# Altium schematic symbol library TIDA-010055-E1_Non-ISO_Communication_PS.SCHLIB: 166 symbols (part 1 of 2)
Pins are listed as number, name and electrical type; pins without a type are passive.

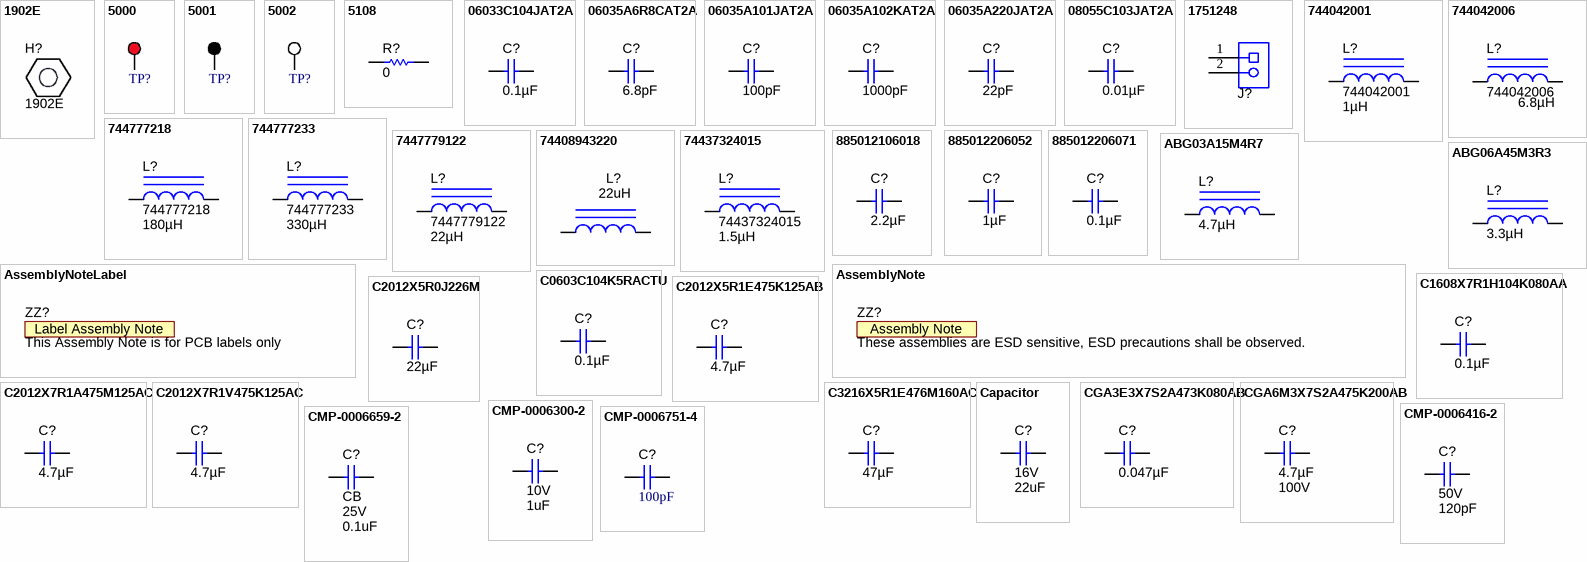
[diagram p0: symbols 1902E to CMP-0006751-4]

## 1902E
designator H?
Standoff, Hex, 1"L #4-40 Nylon; Manufacturer: Keystone; CompType: Hardware; SymbolCreator: a0412235
footprint Keystone_1902E

## 5000
designator TP?  (value not drawn)
Test Point, Miniature, Red, TH; Manufacturer: Keystone; CompType: Test Point Loop; ContactFinish: Silver; Green_Lifecycle: Active; Green_REACh: Passed
footprint Keystone5000
pins: 1

## 5001
designator TP?  (value not drawn)
Test Point, Miniature, Black, TH; Manufacturer: Keystone; CompType: Test Point Loop; ContactFinish: Silver; Green_Lifecycle: Active; Green_REACh: Passed
footprint Keystone5001
pins: 1

## 5002
designator TP?  (value not drawn)
Test Point, Miniature, White, TH; Manufacturer: Keystone; CompType: Test Point Loop; ContactFinish: Silver; Green_Lifecycle: Active; Green_REACh: Passed
footprint Keystone5002
pins: 1

## 5108
designator R?  ValueDisplayed: 0  (hidden comment: 5108)
RES, 0, 1%, 0.5 W, 1206; Manufacturer: Keystone; CompType: Resistor; Value: 0; Tolerance_%: 1; Power_W: 0.5; Value2: 0.5W; TempCo: ppm/C; SizeArea_mm2: 5.185; SizeX_mm: 3.05; SizeY_mm: 1.7; SizeZ_mm: 0.84; U/M: EA; AEC Category: Q200; AEC Qualified: N
signal-integrity model Resistor
simulation model Resistor
footprint 5108
pins: 1, 2

## 06033C104JAT2A
designator C?, comment ValueDisplayed: 0.1µF  (hidden comment: GMK107BJ104KAHT)
0.1µF ±10% 35V Ceramic Capacitor X5R 0603; Manufacturer: Taiyo Yuden; Polarized: N; Value: 0.1uF; U/M: EA; Cap_F: 0.0000001; Tolerance_%: 5; ESR_ohm: 0.05; Value1: 0.05 ohm; VDC_V: 25; Value2: 25V; TempCo: X7R; TaMin_C: -55; TaMax_C: 125; Cap_Case: 0603; SizeArea_mm2: 1.28; SizeAreaWB_mm2: 4.68; SizeX_mm: 1.6; SizeY_mm: 0.8; SizeZ_mm: 1; AEC Category: Q200
signal-integrity model Cap
simulation model Cap
footprint 0603
footprint 0603M
footprint 0603L
footprint 0603_HV
footprint 0603S
pins: 1, 2

## 06035A6R8CAT2A
designator C?  ValueDisplayed: 6.8pF  (hidden comment: 06035A6R8CAT2A)
CAP, CERM, 6.8 pF, 50 V,+/- 4%, C0G/NP0, 0603; Manufacturer: AVX; Polarized: N; CompType: Capacitor; Value: 6.8pF; U/M: EA; Cap_F: 0.0000000000068; Tolerance_%: 4; ESR_ohm: 0.505; Value1: 0.505 ohm; VDC_V: 50; Value2: 50V; TaMin_C: -55; TaMax_C: 125; Cap_Case: 0603; SizeArea_mm2: 1.28; SizeAreaWB_mm2: 4.68; SizeX_mm: 1.6; SizeY_mm: 0.8; SizeZ_mm: 1; AEC Category: Q200; Green_Lifecycle: Active; Green_REACh: Passed
signal-integrity model Cap
simulation model Cap
footprint 0603
footprint 0603M
footprint 0603L
footprint 0603_HV
footprint 0603S
pins: 1, 2

## 06035A101JAT2A
designator C?, comment ValueDisplayed: 100pF  (hidden comment: 06031A101GAT2A)
CAP, CERM, 100 pF, 50 V, +/- 5%, C0G/NP0, 0603; Manufacturer: AVX; Polarized: N; CompType: Capacitor; Value: 100pF; U/M: EA; Cap_F: 0.0000000001; Tolerance_%: 5; ESR_ohm: 0.119; Value1: 0.119 ohm; VDC_V: 50; Value2: 50V; TaMin_C: -55; TaMax_C: 125; Cap_Case: 0603; SizeArea_mm2: 1.28; SizeAreaWB_mm2: 4.68; SizeX_mm: 1.6; SizeY_mm: 0.8; SizeZ_mm: 1; AEC Category: Q200
signal-integrity model Cap
simulation model Cap
footprint 0603
footprint 0603M
footprint 0603L
footprint 0603_HV
footprint 0603S
pins: 1, 2

## 06035A102KAT2A
designator C?  ValueDisplayed: 1000pF  (hidden comment: 06035A102KAT2A)
CAP, CERM, 1000 pF, 50 V,+/- 10%, C0G/NP0, 0603; Manufacturer: AVX; Polarized: N; CompType: Capacitor; Value: 1000pF; U/M: EA; Cap_F: 0.000000001; Tolerance_%: 10; ESR_ohm: 0.048; Value1: 0.048 ohm; VDC_V: 50; Value2: 50V; TaMin_C: -55; TaMax_C: 125; Cap_Case: 0603; SizeArea_mm2: 1.28; SizeAreaWB_mm2: 4.68; SizeX_mm: 1.6; SizeY_mm: 0.8; SizeZ_mm: 1; AEC Category: Q200; Green_Lifecycle: Active; Green_REACh: Passed
signal-integrity model Cap
simulation model Cap
footprint 0603
footprint 0603M
footprint 0603L
footprint 0603_HV
footprint 0603S
pins: 1, 2

## 06035A220JAT2A
designator C?  ValueDisplayed: 22pF  (hidden comment: 06035A220JAT2A)
CAP, CERM, 22 pF, 50 V,+/- 5%, C0G/NP0, 0603; Manufacturer: AVX; Polarized: N; CompType: Capacitor; Value: 22pF; U/M: EA; Cap_F: 0.000000000022; Tolerance_%: 5; ESR_ohm: 0.259; Value1: 0.259 ohm; VDC_V: 50; Value2: 50V; TaMin_C: -55; TaMax_C: 125; Cap_Case: 0603; SizeArea_mm2: 1.28; SizeAreaWB_mm2: 4.68; SizeX_mm: 1.6; SizeY_mm: 0.8; SizeZ_mm: 1; AEC Category: Q200; Green_Lifecycle: Active; Green_REACh: Passed
signal-integrity model Cap
simulation model Cap
footprint 0603
footprint 0603M
footprint 0603L
footprint 0603_HV
footprint 0603S
pins: 1, 2

## 08055C103JAT2A
designator C?  ValueDisplayed: 0.01µF  (hidden comment: 08055C103JAT2A)
CAP, CERM, 0.01 µF, 50 V,+/- 5%, X7R, 0805; Manufacturer: AVX; Polarized: N; CompType: Capacitor; Value: 0.01uF; U/M: EA; Cap_F: 0.00000001; Tolerance_%: 5; ESR_ohm: 0.078; Value1: 0.078 ohm; VDC_V: 50; Value2: 50V; TaMin_C: -55; TaMax_C: 125; Cap_Case: 0805; SizeArea_mm2: 2.5; SizeAreaWB_mm2: 6.75; SizeX_mm: 2; SizeY_mm: 1.25; SizeZ_mm: 1.45; AEC Category: Q200; Green_Lifecycle: Active; Green_REACh: Passed
signal-integrity model Cap
simulation model Cap
footprint 0805_HV
footprint 0805_HV1
footprint 0805
footprint 0805M
footprint 0805L
pins: 1, 2

## 1751248
designator J?  (value not drawn)
Conn Term Block, 2POS, 3.5mm, TH; Manufacturer: Phoenix Contact; CompType: Terminal Block; SymbolCreator: a0412235
footprint CONN_1751248
pins: 1, 2

## 744042001
designator L?  ValueDisplayed: 1µH
Inductor, Shielded Drum Core, Ferrite, 1uH, 2.6A, 0.028 ohm, SMD; Manufacturer: Wurth Elektronik eiSos; Ind_H: 1.0E-6; Imax_A: 2.6; Irms: 2.7A @ 30C rise; Isat: 2.6A @ 35% inductance drop; DCR_ohm: 0.028; U/M: EA
signal-integrity model Inductor
simulation model Inductor
footprint WE-TPC-M1
pins: 1, 2

## 744042006
designator L?  ValueDisplayed: 6.8µH
Inductor, Shielded Drum Core, Ferrite, 6.8uH, 1.2A, 0.095 ohm, SMD; Manufacturer: Wurth Elektronik eiSos; Ind_H: 6.8E-6; Imax_A: 1.2; Irms: 1.5A @ 30C rise; Isat: 1.2A @ 35% inductance drop; DCR_ohm: 0.095; U/M: EA
signal-integrity model Inductor
simulation model Inductor
footprint WE-TPC-M1
pins: 1, 2

## 744777218
designator L?  ValueDisplayed: 180µH
Inductor, Shielded Drum Core, Metal Composite, 180uH, 0.51A, 0.68 ohm, SMD; Manufacturer: Wurth Elektronik eiSos; Ind_H: 180.0E-6; Imax_A: 0.51; Irms: 0.51A @ 40C rise; Isat: 0.56A @ 10% inductance drop; DCR_ohm: 0.68; U/M: EA
signal-integrity model Inductor
simulation model Inductor
footprint WE-PD-M
pins: 1, 2

## 744777233
designator L?  ValueDisplayed: 330µH
Inductor, Shielded Drum Core, Metal Composite, 330uH, 0.39A, 1.15 ohm, SMD; Manufacturer: Wurth Elektronik eiSos; Ind_H: 330.0E-6; Imax_A: 0.39; Irms: 0.39A @ 40C rise; Isat: 0.45A @ 10% inductance drop; DCR_ohm: 1.15; U/M: EA
signal-integrity model Inductor
simulation model Inductor
footprint WE-PD-M
pins: 1, 2

## 7447779122
designator L?  ValueDisplayed: 22µH
Inductor, Shielded Drum Core, Ferrite, 22uH, 1.41A, 0.09 ohm, SMD; Manufacturer: Wurth Elektronik eiSos; Ind_H: 22.0E-6; Imax_A: 1.41; Irms: 1.41A @ 40C rise; Isat: 1.7A @ 10% inductance drop; DCR_ohm: 0.09; U/M: EA
signal-integrity model Inductor
simulation model Inductor
footprint WE-PD-M
pins: 1, 2

## 74408943220
designator L?  value 22uH  (hidden comment: 74408943220)
Inductor, Shielded Drum Core, Ferrite, 22 µH, 1.1 A, 0.185 ohm, SMD; Manufacturer: Wurth Elektronik; Ind_H: 22.0E-6; ValueDisplayed: 22µH; Imax_A: 1.1; Irms: 1.1A @ 40C rise; Isat: 1.4A @ 35% inductance drop; DCR_ohm: 0.185; Value2: 1.1A
signal-integrity model Inductor
simulation model Inductor
footprint WE-SPC_4838
pins: 1, 2

## 74437324015
designator L?  ValueDisplayed: 1.5µH
Inductor, Shielded Drum Core, Powdered Iron, 1.5uH, 3.8A, 0.0348 ohm, SMD; Manufacturer: Wurth Elektronik eiSos; Ind_H: 1.5E-6; Imax_A: 3.8; Irms: 3.8A @ 40C rise; Isat: 8A @ 20% inductance drop; DCR_ohm: 0.0348; U/M: EA
signal-integrity model Inductor
simulation model Inductor
footprint IND_WE-LHMI-4020
pins: 1, 2

## 885012106018
designator C?  ValueDisplayed: 2.2µF  (hidden comment: 885012106018)
CAP, CERM, 2.2 µF, 16 V,+/- 20%, X5R, 0603; Manufacturer: Wurth Elektronik; Polarized: N; CompType: Capacitor; Value: 2.2uF; U/M: EA; Cap_F: 0.0000022; Tolerance_%: 20; VDC_V: 16; Value2: 16V; TaMin_C: -55; TaMax_C: 85; Cap_Case: 0603; SizeArea_mm2: 1.28; SizeAreaWB_mm2: 4.68; SizeX_mm: 1.6; SizeY_mm: 0.8; SizeZ_mm: 1; AEC Category: Q200; Green_Lifecycle: Not Set; Green_REACh: Incomplete
signal-integrity model Cap
simulation model Cap
footprint 0603
footprint 0603M
footprint 0603L
footprint 0603_HV
footprint 0603S
pins: 1, 2

## 885012206052
designator C?  ValueDisplayed: 1µF  (hidden comment: 885012206052)
CAP, CERM, 1 µF, 16 V,+/- 10%, X7R, 0603; Manufacturer: Wurth Elektronik; Polarized: N; CompType: Capacitor; Value: 1uF; U/M: EA; Cap_F: 0.000001; Tolerance_%: 10; Value1: Unknown; VDC_V: 16; Value2: 16V; TaMin_C: -55; TaMax_C: 125; Cap_Case: 0603; SizeArea_mm2: 1.28; SizeAreaWB_mm2: 4.68; SizeX_mm: 1.6; SizeY_mm: 0.8; SizeZ_mm: 1; AEC Category: Q200; Green_Lifecycle: Active; Green_REACh: Passed
signal-integrity model Cap
simulation model Cap
footprint 0603
footprint 0603M
footprint 0603L
footprint 0603_HV
footprint 0603S
pins: 1, 2

## 885012206071
designator C?  ValueDisplayed: 0.1µF  (hidden comment: 885012206071)
CAP, CERM, 0.1 µF, 25 V, +/- 10%, X7R, 0603; Manufacturer: Wurth Elektronik; Polarized: N; CompType: Capacitor; Value: 0.1uF; U/M: EA; Cap_F: 0.0000001; Tolerance_%: 10; Value1: Unknown; VDC_V: 25; Value2: 25V; TaMin_C: -55; TaMax_C: 125; Cap_Case: 0603; AEC Category: Q200
signal-integrity model Cap
simulation model Cap
footprint 0603
footprint 0603M
footprint 0603L
footprint 0603_HV
footprint 0603S
pins: 1, 2

## ABG03A15M4R7
designator L?  ValueDisplayed: 4.7µH  (hidden comment: ABG03A15M4R7)
Inductor, 4.7 µH, 1.12 A, 0.12 ohm, SMD; Manufacturer: Coilank; Value: 4.7uH; Ind_H: 4.7E-6; Imax_A: 1.12; Irms: 1.12A @ 40C rise; Isat: 1.13A @ 35% inductance drop; DCR_ohm: 0.12; Value2: 1.12A; AEC Category: Q200; AEC Qualified: N; SizeAreaWB_mm2: 16; SizeArea_mm2: 9; SizeX_mm: 3; SizeZ_mm: 1.5
signal-integrity model Inductor
simulation model Inductor
footprint ABG03A15
pins: 1, 2

## ABG06A45M3R3
designator L?  ValueDisplayed: 3.3µH  (hidden comment: ABG06A45M3R3)
Inductor, 3.3 µH, 3.91 A, 0.026 ohm, SMD; Manufacturer: Coilank; Value: 3.3uH; Ind_H: 3.3E-6; Imax_A: 3.91; Irms: 3.81A @ 40C rise; Isat: 6.08A @ 35% inductance drop; DCR_ohm: 0.026; Value2: 3.91A; AEC Category: Q200; AEC Qualified: N; SizeAreaWB_mm2: 64; SizeArea_mm2: 36; SizeX_mm: 6; SizeZ_mm: 4.5
signal-integrity model Inductor
simulation model Inductor
footprint ABG06A45
pins: 1, 2

## AssemblyNote
designator ZZ?, comment These assemblies are ESD sensitive, ESD precautions shall be observed.  (no BOM)
SymbolCreator: codlsc; CompType: AssemblyNote
footprint AssemblyNote

## AssemblyNoteLabel
designator ZZ?, comment This Assembly Note is for PCB labels only  (no BOM)
SymbolCreator: a0412235
footprint AssemblyNoteLabel

## C0603C104K5RACTU
designator C?, comment ValueDisplayed: 0.1µF  (hidden comment: C0603C104K5RECAUTO)
CAP, CERM, 0.1µF ±10% 50V Ceramic Capacitor X7R 0603; Manufacturer: Kemet; Polarized: N; Value: 0.1uF; U/M: EA; Cap_F: 0.0000001; Tolerance_%: 10; VDC_V: 50; TaMin_C: -55; TaMax_C: 125; Cap_Case: 0603; SizeArea_mm2: 1.28; SizeAreaWB_mm2: 4.68; SizeX_mm: 1.6; SizeY_mm: 0.8; SizeZ_mm: 1; AEC Category: Q200; Green_Lifecycle: Active; Green_REACh: Passed
signal-integrity model Cap
simulation model Cap
footprint 0603
footprint 0603M
footprint 0603L
footprint 0603_HV
footprint 0603S
pins: 1, 2

## C1608X7R1H104K080AA
designator C?  ValueDisplayed: 0.1µF  (hidden comment: C1608X7R1H104K080AA)
CAP, CERM, 0.1 µF, 50 V, +/- 10%, X7R, 0603; Manufacturer: TDK; Polarized: N; CompType: Capacitor; Value: 0.1uF; U/M: EA; Cap_F: 0.0000001; Tolerance_%: 10; ESR_ohm: 0.0296; Value1: 0.0296 ohm; VDC_V: 50; Value2: 50V; IRMS_A: 0.97199; TaMin_C: -55; TaMax_C: 125; Cap_Case: 0603; SizeArea_mm2: 1.28; SizeAreaWB_mm2: 4.68; SizeX_mm: 1.6; SizeY_mm: 0.8; SizeZ_mm: 1; AEC Category: Q200
signal-integrity model Cap
simulation model Cap
footprint 0603
footprint 0603M
footprint 0603L
footprint 0603_HV
footprint 0603S
pins: 1, 2

## C2012X5R0J226M
designator C?  ValueDisplayed: 22µF  (hidden comment: C2012X5R0J226M)
CAP, CERM, 22 µF, 6.3 V, +/- 20%, X5R, 0805; Manufacturer: TDK; Polarized: N; CompType: Capacitor; Value: 22uF; U/M: EA; Cap_F: 0.000022; Tolerance_%: 20; ESR_ohm: 0.0018; Value1: 0.0018 ohm; VDC_V: 6.3; Value2: 6.3V; TaMin_C: -55; TaMax_C: 85; Cap_Case: 0805
signal-integrity model Cap
simulation model Cap
footprint 0805_HV (0805 with 30mil clearance between pads)
footprint 0805
footprint 0805M
footprint 0805L
pins: 1, 2

## C2012X5R1E475K125AB
designator C?  ValueDisplayed: 4.7µF  (hidden comment: C2012X5R1E475K125AB)
CAP, CERM, 4.7 µF, 25 V, +/- 10%, X5R, 0805; Manufacturer: TDK; Polarized: N; CompType: Capacitor; Value: 4.7uF; U/M: EA; Cap_F: 0.0000047; Tolerance_%: 10; Value1: Unknown; VDC_V: 25; Value2: 25V; TaMin_C: -55; TaMax_C: 85; Cap_Case: 0805
signal-integrity model Cap
simulation model Cap
footprint 0805_HV
footprint 0805
footprint 0805M
footprint 0805L
pins: 1, 2

## C2012X7R1A475M125AC
designator C?  ValueDisplayed: 4.7µF  (hidden comment: C2012X7R1A475M125AC)
CAP, CERM, 4.7 µF, 10 V,+/- 20%, X7R, 0805; Manufacturer: TDK; Polarized: N; CompType: Capacitor; Value: 4.7uF; U/M: EA; Cap_F: 0.0000047; Tolerance_%: 20; VDC_V: 10; Value2: 10V; TaMin_C: -55; TaMax_C: 125; Cap_Case: 0805; SizeArea_mm2: 2.5; SizeAreaWB_mm2: 6.75; SizeX_mm: 2; SizeY_mm: 1.25; SizeZ_mm: 1.45; AEC Category: Q200; Green_Lifecycle: Active; Green_REACh: Passed
signal-integrity model Cap
simulation model Cap
footprint 0805_HV
footprint 0805_HV1
footprint 0805
footprint 0805M
footprint 0805L
pins: 1, 2

## C2012X7R1V475K125AC
designator C?  ValueDisplayed: 4.7µF  (hidden comment: C2012X7R1V475K125AC)
CAP, CERM, 4.7 µF, 35 V, +/- 10%, X7R, 0805; Manufacturer: TDK; Polarized: N; CompType: Capacitor; Value: 4.7uF; U/M: EA; Cap_F: 0.0000047; Tolerance_%: 10; ESR_ohm: 0.002346; Value1: 0.002346 ohm; VDC_V: 35; Value2: 35V; IRMS_A: 4.26021; TaMin_C: -55; TaMax_C: 125; Cap_Case: 0805; AEC Category: Q200; SizeArea_mm2: 2.5; SizeAreaWB_mm2: 6.75; SizeX_mm: 2; SizeY_mm: 1.25; SizeZ_mm: 1.45
signal-integrity model Cap
simulation model Cap
footprint 0805_HV
footprint 0805_HV1
footprint 0805
footprint 0805M
footprint 0805L
pins: 1, 2

## C3216X5R1E476M160AC
designator C?  ValueDisplayed: 47µF  (hidden comment: C3216X5R1E476M160AC)
CAP, CERM, 47 µF, 25 V,+/- 20%, X5R, 1206; Manufacturer: TDK; Polarized: N; CompType: Capacitor; Value: 47uF; U/M: EA; Cap_F: 0.000047; Tolerance_%: 20; VDC_V: 25; Value2: 25V; TaMin_C: -55; TaMax_C: 85; Cap_Case: 1206; SizeArea_mm2: 5.12; SizeAreaWB_mm2: 10.92; SizeX_mm: 3.2; SizeY_mm: 1.6; SizeZ_mm: 1.9; AEC Category: Q200; Green_Lifecycle: Active; Green_REACh: Passed
signal-integrity model Cap
simulation model Cap
footprint 1206_190
footprint 1206_190M
footprint 1206_190L
pins: 1, 2

## Capacitor
designator C?, comment VDC_V: 16V  ValueDisplayed: 22uF  (hidden comment: EMK316BB7226ML-T)
CAP, CERM, 22 uF, 16 V, +/- 20%, X7R, 1206_190; Manufacturer: Taiyo Yuden; TaMin_C: -55°C; Polarized: N; SizeAreaWB_mm2: 10.92; Value1: Unknown; U/M: EA; Value: 22uF; TaMax_C: 125°C; SizeZ_mm: 1.9; SizeX_mm: 3.2; SizeY_mm: 1.6; Cap_Case: 1206; SizeArea_mm2: 5.12; CompType: Capacitor; Cap_F: 22µF; AEC Category: Q200
footprint 1206_190
footprint 1206_190L (1206_190)
footprint 1206_190M (1206_190)
pins: 1, 2

## CGA3E3X7S2A473K080AB
designator C?, comment ValueDisplayed: 0.047µF  (hidden comment: CIN3)
CAP, CERM, 0.047 µF, 100 V,+/- 10%, X7S, AEC-Q200 Grade 1, 0603; PartNumber: CGA3E3X7S2A473K080AB; Manufacturer: TDK; Polarized: N; CompType: Capacitor; Value: 0.047uF; U/M: EA; Cap_F: 0.000000047; Tolerance_%: 10; ESR_ohm: 0.089796; Value1: 0.089796 ohm; VDC_V: 100; Value2: 100V; IRMS_A: 0.567484; TaMin_C: -55; TaMax_C: 125; Cap_Case: 0603; SizeArea_mm2: 1.28; SizeAreaWB_mm2: 4.68; SizeX_mm: 1.6; SizeY_mm: 0.8; SizeZ_mm: 1; AEC Category: Q200; AEC Qualified: Y
signal-integrity model Cap
simulation model Cap
footprint 0603
footprint 0603M
footprint 0603L
footprint 0603_HV
footprint 0603S
pins: 1, 2

## CGA6M3X7S2A475K200AB
designator C?, comment ValueDisplayed: 4.7µF  Value2: 100V  (hidden comment: CIN2)
CAP, CERM, 4.7 µF, 100 V, +/- 10%, X7S, AEC-Q200 Grade 1, 1210; PartNumber: CGA6M3X7S2A475K200AB; Manufacturer: TDK; Polarized: N; CompType: Capacitor; Value: 4.7uF; U/M: EA; Cap_F: 0.0000047; Tolerance_%: 10; ESR_ohm: 0.004236; Value1: 0.004236 ohm; VDC_V: 100; IRMS_A: 3.57337; TaMin_C: -55; TaMax_C: 125; Cap_Case: 1210_220; SizeArea_mm2: 8; SizeAreaWB_mm2: 14.7; SizeX_mm: 3.2; SizeY_mm: 2.5; SizeZ_mm: 2.2; AEC Category: Q200; AEC Qualified: Y; AEC Grade: 1
signal-integrity model Cap
simulation model Cap
footprint 1210_220
footprint 1210_220M
footprint 1210_220L
pins: 1, 2

## CMP-0006300-2
designator C?, comment VDC_V: 10V  ValueDisplayed: 1uF  (hidden comment: C1005X7S1A105K050BC)
CAP, CERM, 1 uF, 10 V, +/- 10%, X7S, 0402; Manufacturer: TDK; TaMin_C: -55°C; ESR_ohm: 0.011416; Polarized: N; SizeAreaWB_mm2: 3; Value1: 0.011416 ohm; U/M: EA; Value: 1uF; TaMax_C: 125°C; SizeZ_mm: 0.6; SizeX_mm: 1; SizeY_mm: 0.5; Cap_Case: 0402; CompType: Capacitor; Cap_F: 1µF; IRMS_A: 1.483A; AEC Category: Q200
footprint 0402 (0402 from SM-752 data)
footprint 0402S (Based on C0402S footprint from PADS legacy)
footprint 0402L (0402 from SM-752 data)
footprint 0402M (0402 from SM-752 data)
pins: 1, 2

## CMP-0006416-2
designator C?, comment VDC_V: 50V  ValueDisplayed: 120pF  (hidden comment: GRM1555C1H121FA01D)
CAP, CERM, 120 pF, 50 V, +/- 1%, C0G/NP0, 0402; Manufacturer: MuRata; TaMin_C: -55°C; Polarized: N; SizeAreaWB_mm2: 3; Value1: Unknown; U/M: EA; Value: 120pF; TaMax_C: 125°C; SizeZ_mm: 0.6; SizeX_mm: 1; SizeY_mm: 0.5; Cap_Case: 0402; CompType: Capacitor; AEC Category: Q200
footprint 0402 (0402 from SM-752 data)
footprint 0402S (Based on C0402S footprint from PADS legacy)
footprint 0402L (0402 from SM-752 data)
footprint 0402M (0402 from SM-752 data)
pins: 1, 2

## CMP-0006659-2
designator C?, comment CB  VDC_V: 25V  ValueDisplayed: 0.1uF
CAP, CERM, 0.1 uF, 25 V, +/- 10%, X7R, 0402; Manufacturer: MuRata; PartNumber: GRM155R71E104KE14D; TaMin_C: -55°C; Polarized: N; SizeAreaWB_mm2: 3; Value1: Unknown; U/M: EA; Value: 0.1uF; TaMax_C: 125°C; SizeZ_mm: 0.6; SizeX_mm: 1; SizeY_mm: 0.5; Cap_Case: 0402; CompType: Capacitor; Cap_F: 100nF; AEC Category: Q200
footprint 0402 (0402 from SM-752 data)
footprint 0402S (Based on C0402S footprint from PADS legacy)
footprint 0402L (0402 from SM-752 data)
footprint 0402M (0402 from SM-752 data)
pins: 1, 2

## CMP-0006751-4
designator C?, comment ValueDisplayed: 100pF  (hidden comment: 06033C101KAT2A)
CAP, CERM, 100 pF, 25 V, +/- 10%, X7R, 0603; Manufacturer: AVX; TaMin_C: -55°C; Polarized: N; SizeAreaWB_mm2: 4.68; Value1: Unknown; U/M: EA; Value: 100pF; TaMax_C: 125°C; SizeZ_mm: 1; SizeX_mm: 1.6; SizeY_mm: 0.8; Cap_Case: 0603; Value2: 25V; SizeArea_mm2: 1.28; CompType: Capacitor; AEC Category: Q200
footprint 0603 (0603 from SM-752 data)
footprint 0603_HV (Ernesto recommended land pattern.  26 mil between pads.)
footprint 0603L (0603 from SM-752 data)
footprint 0603S
footprint 0603M (0603 from SM-752 data)
pins: 1, 2

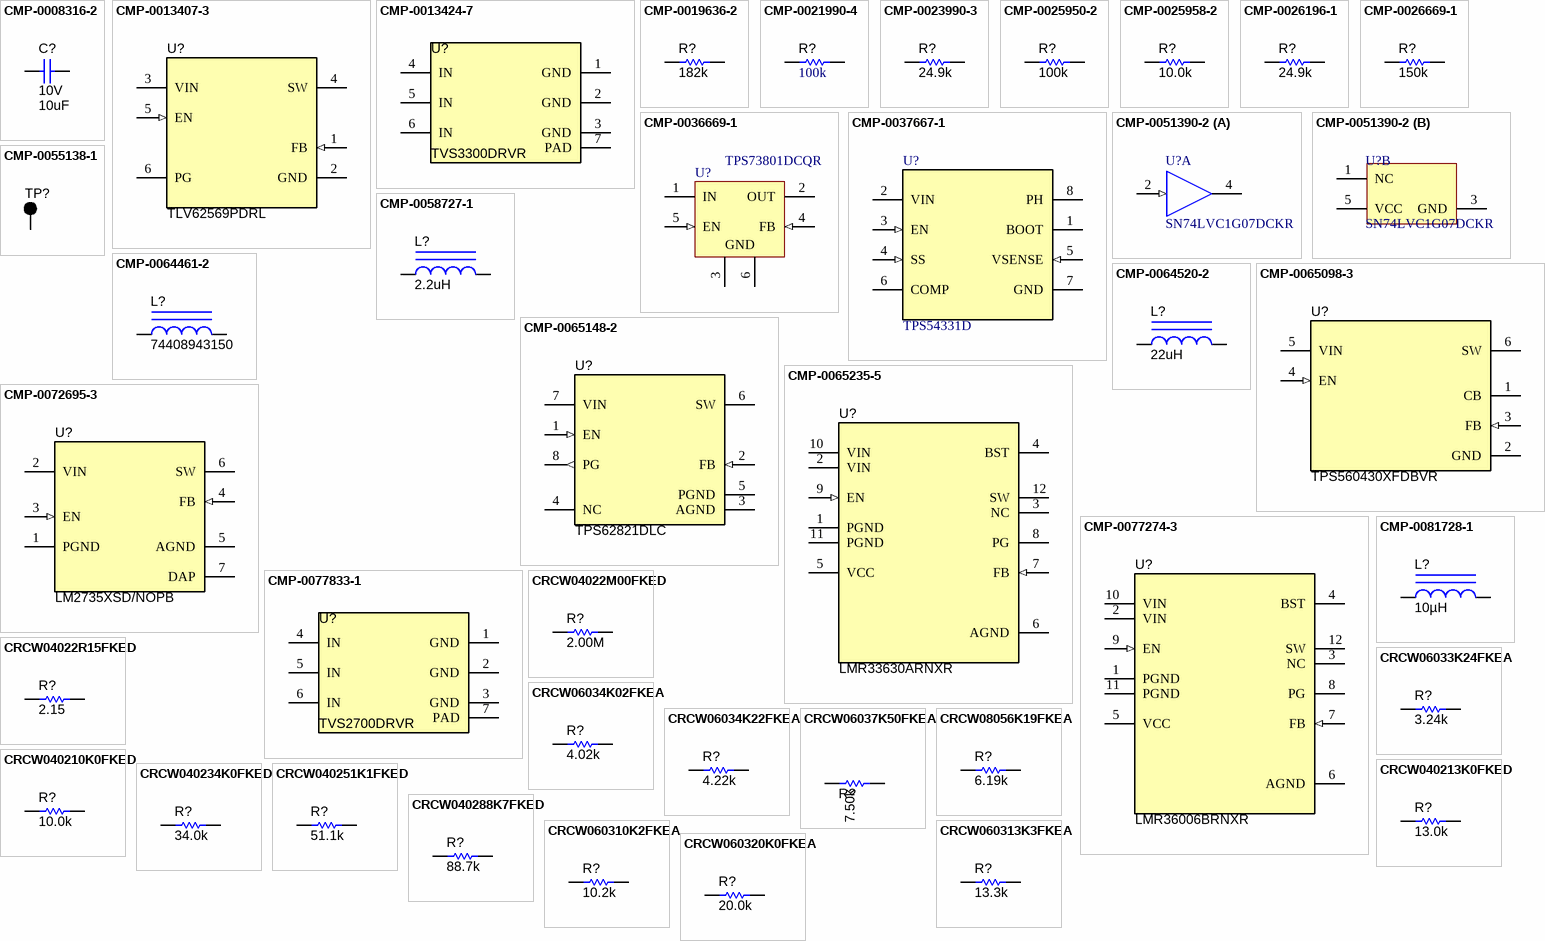
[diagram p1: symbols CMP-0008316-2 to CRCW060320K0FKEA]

## CMP-0008316-2
designator C?, comment VDC_V: 10V  ValueDisplayed: 10uF  (hidden comment: GRM21BR71A106ME51L)
CAP, CERM, 10 uF, 10 V, +/- 20%, X7R, 0805; Manufacturer: MuRata; TaMin_C: -55°C; Polarized: N; SizeAreaWB_mm2: 6.75; Value1: Unknown; U/M: EA; Value: 10uF; TaMax_C: 125°C; SizeZ_mm: 1.45; SizeX_mm: 2; SizeY_mm: 1.25; Cap_Case: 0805; SizeArea_mm2: 2.5; CompType: Capacitor; Cap_F: 10µF; AEC Category: Q200
footprint 0805_HV (0805 with 30mil clearance between pads)
footprint 0805M (0805 from SM-752 data)
footprint 0805 (0805 from SM-752 data)
footprint 0805L (0805 from SM-752 data)
footprint 0805_HV1 (Custom footprint based on analyzing multiple manufacturer recommendations)
pins: 1, 2

## CMP-0013407-3
designator U?, comment TLV62569PDRL
2-A High Efficiency Step-Down Converter in SOT Package, DRL0006A (SOT-6); Manufacturer: Texas Instruments; SizeZ_mm: 0.6; SizeX_mm: 1.6; SizeArea_mm2: 2.56; CompType: IC; U/M: EA; SizeAreaWB_mm2: 6.76
footprint DRL0006A (SOTFL, 6-Flat Leads, Body 1.2x1.6x0.6mm, Pitch 0.5mm, TI recommended)
pins: 1 FB (in), 2 GND (power), 3 VIN (power), 4 SW (power), 5 EN (in), 6 PG (oc)

## CMP-0013424-7
designator U?, comment TVS3300DRVR
33-V Precision Surge Protection Clamp, DRV0006A (WSON-6); Manufacturer: Texas Instruments; Alternate PartNumber: TVS3300DRVT; SizeX_mm: 2; CompType: IC; SizeZ_mm: 0.8; SizeArea_mm2: 4; SizeAreaWB_mm2: 9; U/M: EA
footprint DRV0006A (SON, 6-Leads, Body 2x2mm, Pitch 0.65mm, Thermal Pad 1.6x1mm, TI Recommended)
footprint DRV0006A_NV (SON, 6-Leads, Body 2x2mm, Pitch 0.65mm, Thermal Pad 1.6x1mm, TI Recommended)
pins: 1 GND, 2 GND, 3 GND, 4 IN, 5 IN, 6 IN, 7 PAD
1 alternate drawing of the same symbol

## CMP-0019636-2
designator R?, comment ValueDisplayed: 182k  (hidden comment: RT0805BRD07182KL)
RES, 182 k, 0.1%, 0.125 W, 0805; Manufacturer: Yageo America; Power_W: 125mW; TempCo: 25 ppm/C; U/M: EA; Value: 182k; EIA_Code: E192; SizeX_mm: 2; SizeY_mm: 1.25; SizeZ_mm: 1.45; Value2: 0.125W; SizeArea_mm2: 2.5; CompType: Resistor; VDC_V: 150V; AEC Category: Q200
footprint 0805_HV (0805 with 30mil clearance between pads)
footprint 0805M (0805 from SM-752 data)
footprint 0805 (0805 from SM-752 data)
footprint 0805L (0805 from SM-752 data)
footprint 0805_HV1 (Custom footprint based on analyzing multiple manufacturer recommendations)
pins: 1, 2

## CMP-0021990-4
designator R?, comment ValueDisplayed: 100k  (hidden comment: CRCW0603100KFKEA)
RES, 100 k, 1%, 0.1 W, AEC-Q200 Grade 0, 0603; Manufacturer: Vishay-Dale; Power_W: 100mW; TempCo: 100 ppm/C; Value: 100k; EIA_Code: E96; SizeX_mm: 1.6; SizeY_mm: 0.8; SizeZ_mm: 1; Value2: 0.1W; SizeArea_mm2: 1.28; CompType: Resistor; AEC Qualified: Y; VDC_V: 75V; AEC Category: Q200; AEC Grade: 0
footprint 0603 (0603 from SM-752 data)
footprint 0603_HV (Ernesto recommended land pattern.  26 mil between pads.)
footprint 0603L (0603 from SM-752 data)
footprint 0603S
footprint 0603M (0603 from SM-752 data)
pins: 1, 2

## CMP-0023990-3
designator R?, comment ValueDisplayed: 24.9k  (hidden comment: RT0603BRD0724K9L)
RES, 24.9 k, 0.1%, 0.1 W, 0603; Manufacturer: Yageo America; Power_W: 100mW; TempCo: 25 ppm/C; Value_Code: 24k9; U/M: EA; Value: 24.9k; EIA_Code: E192; SizeX_mm: 1.6; SizeY_mm: 0.8; SizeZ_mm: 1; Value2: 0.1W; SizeArea_mm2: 1.28; CompType: Resistor; VDC_V: 75V; AEC Category: Q200
footprint 0603 (0603 from SM-752 data)
footprint 0603_HV (Ernesto recommended land pattern.  26 mil between pads.)
footprint 0603L (0603 from SM-752 data)
footprint 0603S
footprint 0603M (0603 from SM-752 data)
pins: 1, 2

## CMP-0025950-2
designator R?, comment ValueDisplayed: 100k  (hidden comment: RFBB2)
RES, 100 k, 1%, 0.063 W, 0402; Manufacturer: Vishay-Dale; PartNumber: CRCW0402100KFKED; Power_W: 63mW; TempCo: 100 ppm/C; U/M: EA; Value: 100k; EIA_Code: E96; SizeX_mm: 1; SizeY_mm: 0.5; SizeZ_mm: 0.6; Value2: 0.063W; CompType: Resistor; VDC_V: 50V; AEC Category: Q200
footprint 0402 (0402 from SM-752 data)
footprint 0402S (Based on C0402S footprint from PADS legacy)
footprint 0402L (0402 from SM-752 data)
footprint 0402M (0402 from SM-752 data)
pins: 1, 2

## CMP-0025958-2
designator R?, comment ValueDisplayed: 10.0k  (hidden comment: RPG2)
RES, 10.0 k, 1%, 0.063 W, 0402; Manufacturer: Vishay-Dale; PartNumber: CRCW040210K0FKED; Power_W: 63mW; TempCo: 100 ppm/C; Value_Code: 10k0; U/M: EA; Value: 10.0k; EIA_Code: E96; Res_ohm: 10k; SizeX_mm: 1; SizeY_mm: 0.5; SizeZ_mm: 0.6; Value2: 0.063W; CompType: Resistor; VDC_V: 50V; AEC Category: Q200
footprint 0402 (0402 from SM-752 data)
footprint 0402S (Based on C0402S footprint from PADS legacy)
footprint 0402L (0402 from SM-752 data)
footprint 0402M (0402 from SM-752 data)
pins: 1, 2

## CMP-0026196-1
designator R?, comment ValueDisplayed: 24.9k  (hidden comment: CRCW040224K9FKED)
RES, 24.9 k, 1%, 0.063 W, 0402; Manufacturer: Vishay-Dale; Power_W: 63mW; TempCo: 100 ppm/C; Value_Code: 24k9; U/M: EA; Value: 24.9k; EIA_Code: E96; SizeX_mm: 1; SizeY_mm: 0.5; SizeZ_mm: 0.6; Value2: 0.063W; CompType: Resistor; VDC_V: 50V; AEC Category: Q200
footprint 0402 (0402 from SM-752 data)
footprint 0402S (Based on C0402S footprint from PADS legacy)
footprint 0402L (0402 from SM-752 data)
footprint 0402M (0402 from SM-752 data)
pins: 1, 2

## CMP-0026669-1
designator R?, comment ValueDisplayed: 150k  (hidden comment: ERJ-2RKF1503X)
RES, 150 k, 1%, 0.1 W, AEC-Q200 Grade 0, 0402; Manufacturer: Panasonic; Power_W: 100mW; TempCo: 100 ppm/C; U/M: EA; Value: 150k; EIA_Code: E96; SizeX_mm: 1; SizeY_mm: 0.5; SizeZ_mm: 0.6; Value2: 0.1W; CompType: Resistor; AEC Qualified: Y; VDC_V: 50V; AEC Grade: 0; AEC Category: Q200
footprint 0402 (0402 from SM-752 data)
footprint 0402S (Based on C0402S footprint from PADS legacy)
footprint 0402L (0402 from SM-752 data)
footprint 0402M (0402 from SM-752 data)
pins: 1, 2

## CMP-0036669-1
designator U?, comment TPS73801DCQR
Single Output Fast Transient Response LDO, 1 A, Adjustable 1.2 to 20 V Output, 2.2 to 20 V Input, 6-pin SOT-223 (DCQ), -40 to 125 degC, Green (RoHS & no Sb/Br); Manufacturer: Texas Instruments; Vout Adj(Max)(V): 20; Iout(Max)(A): 1; Vdo(Typ)(mV): 300; SubFamily: Single Channel LDO; Vin(Min)(V): 2.2; Vout Adj(Min)(V): 1.2
footprint DCQ0006A_N (SOT223, 6-Leads, Body 6.6x7.3mm (max), Pitch 1.27mm, IPC Medium Density)
footprint DCQ0006A_M
footprint DCQ0006A_L
pins: 1 IN (power) "Input. Power is supplied to the device through the IN pin. A bypass capacitor is required on this pin if the device is more than six inches away from the main input filter capacitor. In general, the output impedance of a (See Datasheet)", 2 OUT (power) "Output. The output supplies power to the load. A minimum output capacitor (ceramic) of 10 uF is required to prevent oscillations. Larger output capacitors are required for applications with large transient loads to limit (See Datasheet)", 3 GND (power) "Ground", 4 FB (in) "Feedback. This is the input to the error amplifier. This pin is internally clamped to +/-7 V. It has a bias current of 3 uA that flows into the pin. The FB pin voltage is 1.21 V referenced to ground, and the output voltage (See Datasheet)", 5 EN (in) "Enable. The EN pin is used to put the TPS73801 regulators into a low-power shutdown state. The output is off when the EN pin is pulled low. The EN pin can be driven either by 5-V logic or open-collector gate, normally (See Datasheet)", 6 GND (power) "Ground"

## CMP-0037667-1
designator U?, comment TPS54331D
Buck Step Down Regulator with 3.5 to 28 V Input and 0.8 to 25 V Output, -40 to 150 degC, 8-Pin SOIC (D), Green (RoHS & no Sb/Br); Manufacturer: Texas Instruments; Iq(Typ)(mA): 0.11; Duty Cycle(Max)(%): 90; Vout(Max)(V): 25; Rating: Catalog; Vin(Min)(V): 3.5; Iout(Max)(A): 3; Regulated Outputs(#): 1; Vin(Max)(V): 28; Vout(Min)(V): 0.8; SubFamily: Step-Down Regulator
footprint D0008A_N (SOIC, 8-Leads, Body 4.9x3.9mm, Pitch 1.27mm, IPC Medium Density)
footprint D0008A_M (SOIC, 8-Leads, Body 4.9x3.9mm, Pitch 1.27mm, IPC Low Density)
footprint D0008A_L (SOIC, 8-Leads, Body 4.9x3.9mm, Pitch 1.27mm, IPC High Density)
pins: 1 BOOT "A 0.1 uF bootstrap capacitor is required between BOOT and PH. If the voltage on this capacitor falls below the minimum requirement, the high-side MOSFET is forced to switch off until the capacitor is refreshed", 2 VIN (power) "Input supply voltage, 3.5 V to 28 V.", 3 EN (in) "Enable pin. Pull below 1.25V to disable. Float to enable. Programming the input undervoltage lockout with two resistors is recommended.", 4 SS (in) "Slow start pin. An external capacitor connected to this pin sets the output rise time.", 5 VSENSE (in) "Inverting node of the gm error amplifier.", 6 COMP "Error amplifier output, and input to the PWM comparator. Connect frequency compensation components to this pin.", 7 GND (power) "Ground", 8 PH (power) "The source of the internal high-side power MOSFET"

## CMP-0051390-2
designator U?, comment SN74LVC1G07DCKR
Single Buffer/Driver With Open-Drain Output, DCK0005A, LARGE T&R; Manufacturer: Texas Instruments; 3-State Output: No; F @ Nom Voltage(Max)(Mhz): 150; ICC @ Nom Voltage(Max)(mA): 0.01; VCC(Min)(V): 1.65; Logic: True; Sub-Family: Non-Inverting Buffer/Driver; Output Drive (IOL/IOH)(Max)(mA): 32/-32; Input Type: CMOS/TTL; Technology Family: LVC; Bits(#): 1; VCC(Max)(V): 5.5; Output Type: CMOS; tpd @ Nom Voltage(Max)(ns): 8.6,6,4.7,4; Rating: Catalog; Voltage(Nom)(V): 1.8,2.5,3.3,5; AEC Category: Q200; AEC Qualified: N; CompType: IC; SizeAreaWB_mm2: 9.3; SizeArea_mm2: 4.2; SizeX_mm: 2.1; SizeY_mm: 2.0; SizeZ_mm: 1.1
footprint DCK0005A_N (SOT353, 5-Leads, Body 2x1.3mm, Pitch 0.65mm, Lead Span 2.1mm, IPC Medium Density)
footprint DCK0005A_M (SOT353, 5-Leads, Body 2x1.3mm, Pitch 0.65mm, Lead Span 2.1mm, IPC Low Density)
footprint DCK0005A_L (SOT353, 5-Leads, Body 2x1.3mm, Pitch 0.65mm, Lead Span 2.1mm, IPC High Density)
part A pins: 2 A (in) "Input A", 4 Y (oc) "Output Y"
part B pins: 1 NC "No Connection", 3 GND (power) "Ground Pin", 5 VCC (power) "Power Pin"

## CMP-0055138-1
designator TP?, comment 5001  (value not drawn)
Test Point, Miniature, Black, TH; Manufacturer: Keystone; CNHeader: FALSE; Green_Lifecycle: Active; Green_REACh: Passed; ContactFinish: Silver; CT: TRUE
footprint Keystone5001 (For Keystone 500x miniature loop terminals)
pins: 1

## CMP-0058727-1
designator L?, comment ValueDisplayed: 2.2uH  (hidden comment: LQH5BPN2R2NT0L)
Inductor, Wirewound, Ferrite, 2.2 uH, 2.6 A, 0.036 ohm, SMD; Manufacturer: MuRata; Isat: 4A @ 30% inductance drop; Irms: 2.6A @ 40C rise; SizeAreaWB_mm2: 34.81; DCR_ohm: 0.036; Value: 2.2uH; Imax_A: 2.6A; SizeZ_mm: 2.2; SizeX_mm: 4.9; SizeArea_mm2: 24.01; Ind_H: 2.2µH; AEC Qualified: N; AEC Category: Q200
footprint LQH5BPN_20 (MURATA)
pins: 1, 2

## CMP-0064461-2
designator L?, comment 74408943150
Inductor, Shielded Drum Core, Ferrite, 15 uH, 1.4 A, 0.118 ohm, SMD; Manufacturer: Wurth Elektronik; Isat: 1.7A @ 35% inductance drop; Irms: 1.4A @ 40C rise; Green_Lifecycle: Active; SizeAreaWB_mm2: 33.64; DCR_ohm: 1.18d; Green_REACh: Passed; Value: 15uH; Imax_A: 1.4A; SizeZ_mm: 4.1; SizeX_mm: 4.8; SizeArea_mm2: 23.04; Ind_H: 15µH; AEC Category: Q200
footprint WE-SPC_4838 (WURTH)
pins: 1, 2

## CMP-0064520-2
designator L?, comment ValueDisplayed: 22uH  (hidden comment: 7447471220)
Inductor, Shielded Drum Core, Metal Composite, 22 uH, 3 A, 0.038 ohm, TH; Manufacturer: Wurth Elektronik; Isat: 3A @ 10% inductance drop; Irms: 3.7A @ 40C rise; Green_Lifecycle: Active; SizeAreaWB_mm2: 169; DCR_ohm: 0.038; Green_REACh: Passed; Value: 22uH; Imax_A: 3A; SizeZ_mm: 11.5; SizeX_mm: 11; SizeArea_mm2: 121; Ind_H: 22µH; AEC Category: Q200
footprint WE-TIS-1111 (WURTH)
pins: 1, 2

## CMP-0065098-3
designator U?, comment TPS560430XFDBVR
4V to 36 V 0.6 A Synchronous Step-Down Converter, DBV0006A (SOT-23-6); Manufacturer: Texas Instruments; Alternate PartNumber: TPS560430XFDBVT; SizeX_mm: 2.8; SizeY_mm: 2.9; CompType: IC; SizeZ_mm: 1.45; SizeArea_mm2: 8.12; SizeAreaWB_mm2: 14.82; U/M: EA
footprint DBV0006A_N (SOT23, 6-Leads, Body 2.9x1.6mm, Pitch 0.95mm, Lead Span 2.8mm, IPC Medium Density)
footprint DBV0006A_L (SOT23, 6-Leads, Body 2.9x1.6mm, Pitch 0.95mm, Lead Span 2.8mm, IPC High Density)
footprint DBV0006A_M (SOT23, 6-Leads, Body 2.9x1.6mm, Pitch 0.95mm, Lead Span 2.8mm, IPC Low Density)
pins: 1 CB (power), 2 GND (power), 3 FB (in), 4 EN (in), 5 VIN (power), 6 SW (power)

## CMP-0065148-2
designator U?, comment TPS62821DLC
2.5-V to 5.5-V, 1-, 2-, 3-A Step-Down Converter with DCS-Control, DLC0008A (SON-HR-8); Manufacturer: Texas Instruments; SizeX_mm: 1.5; SizeY_mm: 2.0; CompType: IC; SizeZ_mm: 1.0; SizeArea_mm2: 3.0; SizeAreaWB_mm2: 7.5; U/M: EA
footprint DLC0008A (QFN-8 (2.0mmX1.5mm))
pins: 1 EN (in), 2 FB (in), 3 AGND (power), 4 NC, 5 PGND (power), 6 SW (power), 7 VIN (power), 8 PG (out)

## CMP-0065235-5
designator U?, comment LMR33630ARNXR
3.8-V to 36-V 2-A Synchronous Step-Down Voltage Regulator, RNX0012B (VQFN-HR-12); Manufacturer: Texas Instruments; Alternate PartNumber: LMR33630ARNXT; SizeX_mm: 2.0; SizeY_mm: 3.0; CompType: IC; SizeZ_mm: 1.0; SizeArea_mm2: 6.0; SizeAreaWB_mm2: 12.0; AEC Category: Q200; AEC Qualified: N
footprint RNX0012B (VQFN-HR-12)
pins: 1 PGND (power), 2 VIN (power), 3 NC, 4 BST, 5 VCC (power), 6 AGND (power), 7 FB (in), 8 PG (oc), 9 EN (in), 10 VIN (power), 11 PGND (power), 12 SW (power)

## CMP-0072695-3
designator U?, comment LM2735XSD/NOPB
520kHz/1.6MHz - Space-Efficient Boost and SEPIC DC-DC Regulator, 6-pin LLP, Pb-Free; Manufacturer: Texas Instruments; PackageTopMarking: ZXYTT*2735X; CompType: Switcher; PowerWise: N; High-Reliability: Y
footprint NGG0006A (TI recommended footprint)
pins: 1 PGND (power), 2 VIN (power), 3 EN (in), 4 FB (in), 5 AGND (power), 6 SW (power), 7 DAP (power)

## CMP-0077274-3
designator U?, comment LMR36006BRNXR
65-V 0.6-A Synchronous Step-Down Converter, RNX0012B (VQFN-HR-12); Alternate PartNumber: LMR36006BRNXT; Alternate Manufacturer: Texas Instruments; SizeAreaWB_mm2: 12.0; SizeZ_mm: 1.0; SizeX_mm: 2.0; SizeY_mm: 3.0; SizeArea_mm2: 6.0; CompType: IC; AEC Qualified: N; AEC Category: Q200
footprint RNX0012B (VQFN-HR-12)
pins: 1 PGND (power), 2 VIN (power), 3 NC, 4 BST, 5 VCC (power), 6 AGND (power), 7 FB (in), 8 PG (oc), 9 EN (in), 10 VIN (power), 11 PGND (power), 12 SW (power)

## CMP-0077833-1
designator U?, comment TVS2700DRVR
27-V Precision Surge Protection Clamp, DRV0006A (WSON-6); Alternate Manufacturer: Texas Instruments; SizeAreaWB_mm2: 9.0; SizeZ_mm: 0.8; SizeX_mm: 2.0; SizeArea_mm2: 4.0; CompType: IC; AEC Qualified: N; AEC Category: Q200
footprint DRV0006A (SON, 6-Leads, Body 2x2mm, Pitch 0.65mm, Thermal Pad 1.6x1mm, TI Recommended)
footprint DRV0006A_NV (SON, 6-Leads, Body 2x2mm, Pitch 0.65mm, Thermal Pad 1.6x1mm, TI Recommended)
pins: 1 GND, 2 GND, 3 GND, 4 IN, 5 IN, 6 IN, 7 PAD
1 alternate drawing of the same symbol

## CMP-0081728-1
designator L?, comment ValueDisplayed: 10µH  (hidden comment: 74438357100)
Inductor, Shielded, Metal Composite, 10 µH, 2.7 A, 0.11 ohm, SMD; Manufacturer: Wurth Elektronik; SizeAreaWB_mm2: 26.01; Irms: 2.7A @ 40C rise; SizeArea_mm2: 16.81; AEC Qualified: N; AEC Category: Q200; Value: 10uH; SizeZ_mm: 3.1; Imax_A: 2.7A; SizeY_mm: 4.1; Isat: 4.6A @ 20% inductance drop; DCR_ohm: 0.11
footprint WE-MAPI_4030 (SMD, 2-Leads, Body 4.1x4.1mm)
pins: 1, 2

## CRCW04022M00FKED
designator R?  ValueDisplayed: 2.00M  (hidden comment: CRCW04022M00FKED)
RES, 2.00 M, 1%, 0.063 W, 0402; Manufacturer: Vishay-Dale; CompType: Resistor; Value: 2.00Meg; Res_ohm: 2000000; Value_Code: 2M00; Tolerance_%: 1; Power_W: 0.063; Value2: 0.063W; VDC_V: 50; TempCo: 100 ppm/C; EIA_Code: E96; U/M: EA; AEC Category: Q200
signal-integrity model Resistor
simulation model Resistor
footprint 0402
footprint 0402M
footprint 0402L
footprint 0402S
pins: 1, 2

## CRCW04022R15FKED
designator R?  ValueDisplayed: 2.15  (hidden comment: CRCW04022R15FKED)
RES, 2.15, 1%, 0.063 W, 0402; Manufacturer: Vishay-Dale; CompType: Resistor; Value: 2.15; Value_Code: 2R15; Tolerance_%: 1; Power_W: 0.063; Value2: 0.063W; VDC_V: 50; TempCo: 100 ppm/C; SizeArea_mm2: 0.5; SizeZ_mm: 0.6; EIA_Code: E96; U/M: EA; AEC Category: Q200
signal-integrity model Resistor
simulation model Resistor
footprint 0402
footprint 0402M
footprint 0402L
footprint 0402S
pins: 1, 2

## CRCW06033K24FKEA
designator R?  ValueDisplayed: 3.24k  (hidden comment: CRCW06033K24FKEA)
RES, 3.24 k, 1%, 0.1 W, 0603; Manufacturer: Vishay-Dale; CompType: Resistor; Value: 3.24k; Res_ohm: 3240; Value_Code: 3k24; Tolerance_%: 1; Power_W: 0.1; Value2: 0.1W; VDC_V: 75; TempCo: 100 ppm/C; SizeArea_mm2: 1.28; SizeX_mm: 1.6; SizeY_mm: 0.8; EIA_Code: E96; U/M: EA; AEC Category: Q200; Green_Lifecycle: Active; Green_REACh: Passed
signal-integrity model Resistor
simulation model Resistor
footprint 0603
footprint 0603M
footprint 0603L
footprint 0603_HV
footprint 0603S
pins: 1, 2

## CRCW06034K02FKEA
designator R?  ValueDisplayed: 4.02k  (hidden comment: CRCW06034K02FKEA)
RES, 4.02 k, 1%, 0.1 W, 0603; Manufacturer: Vishay-Dale; CompType: Resistor; Value: 4.02k; Res_ohm: 4020; Value_Code: 4k02; Tolerance_%: 1; Power_W: 0.1; Value2: 0.1W; VDC_V: 75; TempCo: 100 ppm/C; SizeArea_mm2: 1.28; SizeX_mm: 1.6; SizeY_mm: 0.8; EIA_Code: E96; U/M: EA; AEC Category: Q200; Green_Lifecycle: Active; Green_REACh: Passed
signal-integrity model Resistor
simulation model Resistor
footprint 0603
footprint 0603M
footprint 0603L
footprint 0603_HV
footprint 0603S
pins: 1, 2

## CRCW06034K22FKEA
designator R?  ValueDisplayed: 4.22k  (hidden comment: CRCW06034K22FKEA)
RES, 4.22 k, 1%, 0.1 W, 0603; Manufacturer: Vishay-Dale; CompType: Resistor; Value: 4.22k; Res_ohm: 4220; Value_Code: 4k22; Tolerance_%: 1; Power_W: 0.1; Value2: 0.1W; VDC_V: 75; TempCo: 100 ppm/C; SizeArea_mm2: 1.28; SizeX_mm: 1.6; SizeY_mm: 0.8; EIA_Code: E96; U/M: EA; AEC Category: Q200; Green_Lifecycle: Active; Green_REACh: Passed
signal-integrity model Resistor
simulation model Resistor
footprint 0603
footprint 0603M
footprint 0603L
footprint 0603_HV
footprint 0603S
pins: 1, 2

## CRCW06037K50FKEA
designator R?  ValueDisplayed: 7.50k  (hidden comment: CRCW06037K50FKEA)
RES, 7.50 k, 1%, 0.1 W, 0603; Manufacturer: Vishay-Dale; CompType: Resistor; Value: 7.50k; Res_ohm: 7500; Value_Code: 7k50; Tolerance_%: 1; Power_W: 0.1; Value2: 0.1W; VDC_V: 75; TempCo: 100 ppm/C; SizeArea_mm2: 1.28; SizeX_mm: 1.6; SizeY_mm: 0.8; EIA_Code: E96; U/M: EA; AEC Category: Q200
signal-integrity model Resistor
simulation model Resistor
footprint 0603
footprint 0603M
footprint 0603L
footprint 0603_HV
footprint 0603S
pins: 1, 2

## CRCW08056K19FKEA
designator R?  ValueDisplayed: 6.19k  (hidden comment: CRCW08056K19FKEA)
RES, 6.19 k, 1%, 0.125 W, 0805; Manufacturer: Vishay-Dale; CompType: Resistor; Value: 6.19k; Res_ohm: 6190; Value_Code: 6k19; Tolerance_%: 1; Power_W: 0.125; Value2: 0.125W; VDC_V: 150; TempCo: 100 ppm/C; SizeArea_mm2: 2.5; SizeX_mm: 2; SizeY_mm: 1.25; SizeZ_mm: 1.45; EIA_Code: E96; U/M: EA; AEC Category: Q200
signal-integrity model Resistor
simulation model Resistor
footprint 0805_HV
footprint 0805_HV1
footprint 0805
footprint 0805M
footprint 0805L
pins: 1, 2

## CRCW040210K0FKED
designator R?  ValueDisplayed: 10.0k  (hidden comment: CRCW040210K0FKED)
RES, 10.0 k, 1%, 0.063 W, 0402; Manufacturer: Vishay-Dale; CompType: Resistor; Value: 10.0k; Res_ohm: 10000; Value_Code: 10k0; Tolerance_%: 1; Power_W: 0.063; Value2: 0.063W; VDC_V: 50; TempCo: 100 ppm/C; SizeArea_mm2: 0.5; SizeZ_mm: 0.6; EIA_Code: E96; U/M: EA; AEC Category: Q200
signal-integrity model Resistor
simulation model Resistor
footprint 0402
footprint 0402M
footprint 0402L
footprint 0402S
pins: 1, 2

## CRCW040213K0FKED
designator R?  ValueDisplayed: 13.0k  (hidden comment: CRCW040213K0FKED)
RES, 13.0 k, 1%, 0.063 W, 0402; Manufacturer: Vishay-Dale; CompType: Resistor; Value: 13.0k; Res_ohm: 13000; Value_Code: 13k0; Tolerance_%: 1; Power_W: 0.063; Value2: 0.063W; VDC_V: 50; TempCo: 100 ppm/C; SizeArea_mm2: 0.5; SizeZ_mm: 0.6; EIA_Code: E96; U/M: EA; AEC Category: Q200
signal-integrity model Resistor
simulation model Resistor
footprint 0402
footprint 0402M
footprint 0402L
footprint 0402S
pins: 1, 2

## CRCW040234K0FKED
designator R?  ValueDisplayed: 34.0k  (hidden comment: CRCW040234K0FKED)
RES, 34.0 k, 1%, 0.063 W, 0402; Manufacturer: Vishay-Dale; CompType: Resistor; Value: 34.0k; Res_ohm: 34000; Value_Code: 34k0; Tolerance_%: 1; Power_W: 0.063; Value2: 0.063W; VDC_V: 50; TempCo: 100 ppm/C; EIA_Code: E96; U/M: EA; AEC Category: Q200
signal-integrity model Resistor
simulation model Resistor
footprint 0402
footprint 0402M
footprint 0402L
footprint 0402S
pins: 1, 2

## CRCW040251K1FKED
designator R?  ValueDisplayed: 51.1k  (hidden comment: CRCW040251K1FKED)
RES, 51.1 k, 1%, 0.063 W, 0402; Manufacturer: Vishay-Dale; CompType: Resistor; Value: 51.1k; Res_ohm: 51100; Value_Code: 51k1; Tolerance_%: 1; Power_W: 0.063; Value2: 0.063W; VDC_V: 50; TempCo: 100 ppm/C; SizeArea_mm2: 0.5; SizeZ_mm: 0.6; EIA_Code: E96; U/M: EA; AEC Category: Q200
signal-integrity model Resistor
simulation model Resistor
footprint 0402
footprint 0402M
footprint 0402L
footprint 0402S
pins: 1, 2

## CRCW040288K7FKED
designator R?  ValueDisplayed: 88.7k  (hidden comment: CRCW040288K7FKED)
RES, 88.7 k, 1%, 0.063 W, 0402; Manufacturer: Vishay-Dale; CompType: Resistor; Value: 88.7k; Res_ohm: 88700; Value_Code: 88k7; Tolerance_%: 1; Power_W: 0.063; Value2: 0.063W; VDC_V: 50; TempCo: 100 ppm/C; SizeArea_mm2: 0.5; SizeZ_mm: 0.6; EIA_Code: E96; U/M: EA; AEC Category: Q200
signal-integrity model Resistor
simulation model Resistor
footprint 0402
footprint 0402M
footprint 0402L
footprint 0402S
pins: 1, 2

## CRCW060310K2FKEA
designator R?  ValueDisplayed: 10.2k  (hidden comment: CRCW060310K2FKEA)
RES, 10.2 k, 1%, 0.1 W, 0603; Manufacturer: Vishay-Dale; CompType: Resistor; Value: 10.2k; Res_ohm: 10200; Value_Code: 10k2; Tolerance_%: 1; Power_W: 0.1; Value2: 0.1W; VDC_V: 75; TempCo: 100 ppm/C; SizeArea_mm2: 1.28; SizeX_mm: 1.6; SizeY_mm: 0.8; EIA_Code: E96; U/M: EA; AEC Category: Q200; Green_Lifecycle: Active; Green_REACh: Passed
signal-integrity model Resistor
simulation model Resistor
footprint 0603
footprint 0603M
footprint 0603L
footprint 0603_HV
footprint 0603S
pins: 1, 2

## CRCW060313K3FKEA
designator R?  ValueDisplayed: 13.3k  (hidden comment: CRCW060313K3FKEA)
RES, 13.3 k, 1%, 0.1 W, 0603; Manufacturer: Vishay-Dale; CompType: Resistor; Value: 13.3k; Res_ohm: 13300; Value_Code: 13k3; Tolerance_%: 1; Power_W: 0.1; Value2: 0.1W; VDC_V: 75; TempCo: 100 ppm/C; EIA_Code: E96; U/M: EA; AEC Category: Q200
signal-integrity model Resistor
simulation model Resistor
footprint 0603
footprint 0603M
footprint 0603L
footprint 0603_HV
footprint 0603S
pins: 1, 2

## CRCW060320K0FKEA
designator R?  ValueDisplayed: 20.0k  (hidden comment: CRCW060320K0FKEA)
RES, 20.0 k, 1%, 0.1 W, 0603; Manufacturer: Vishay-Dale; CompType: Resistor; Value: 20.0k; Res_ohm: 20000; Value_Code: 20k0; Tolerance_%: 1; Power_W: 0.1; Value2: 0.1W; VDC_V: 75; TempCo: 100 ppm/C; EIA_Code: E96; U/M: EA
signal-integrity model Resistor
simulation model Resistor
footprint 0603
footprint 0603M
footprint 0603L
footprint 0603_HV
footprint 0603S
pins: 1, 2

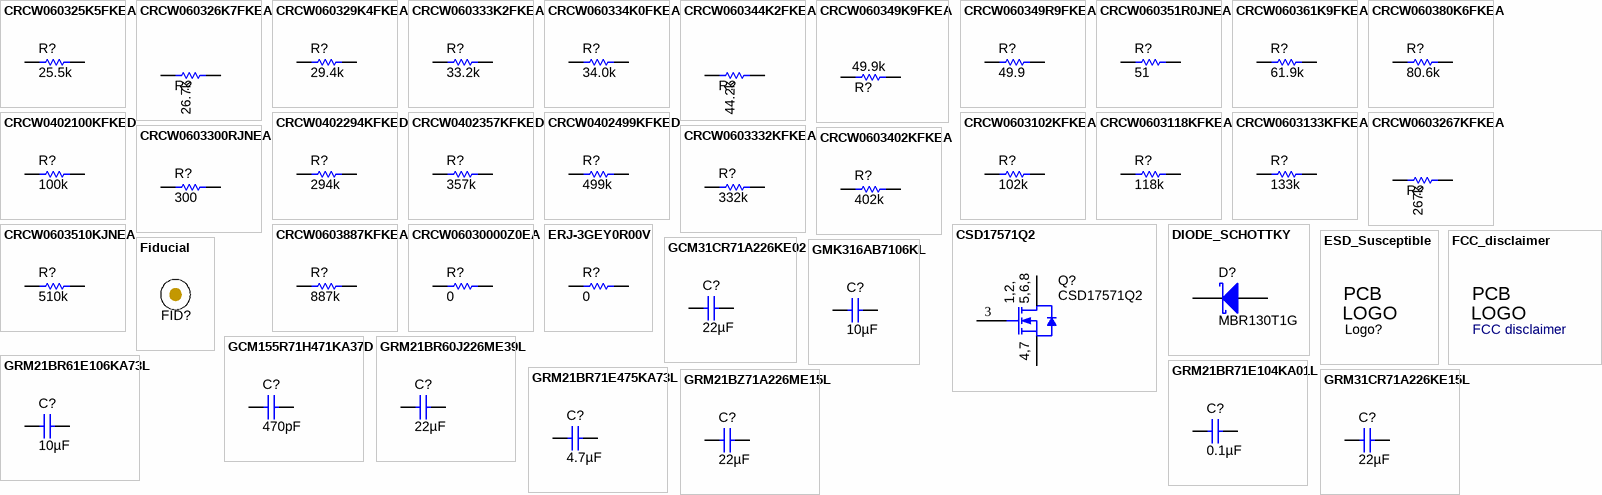
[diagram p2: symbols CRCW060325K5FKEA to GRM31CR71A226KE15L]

## CRCW060325K5FKEA
designator R?  ValueDisplayed: 25.5k  (hidden comment: CRCW060325K5FKEA)
RES, 25.5 k, 1%, 0.1 W, 0603; Manufacturer: Vishay-Dale; CompType: Resistor; Value: 25.5k; Res_ohm: 25500; Value_Code: 25k5; Tolerance_%: 1; Power_W: 0.1; Value2: 0.1W; VDC_V: 75; TempCo: 100 ppm/C; SizeArea_mm2: 1.28; SizeX_mm: 1.6; SizeY_mm: 0.8; EIA_Code: E96; U/M: EA; AEC Category: Q200; Green_Lifecycle: Active; Green_REACh: Passed
signal-integrity model Resistor
simulation model Resistor
footprint 0603
footprint 0603M
footprint 0603L
footprint 0603_HV
footprint 0603S
pins: 1, 2

## CRCW060326K7FKEA
designator R?  ValueDisplayed: 26.7k  (hidden comment: CRCW060326K7FKEA)
RES, 26.7 k, 1%, 0.1 W, 0603; Manufacturer: Vishay-Dale; CompType: Resistor; Value: 26.7k; Res_ohm: 26700; Value_Code: 26k7; Tolerance_%: 1; Power_W: 0.1; Value2: 0.1W; VDC_V: 75; TempCo: 100 ppm/C; SizeArea_mm2: 1.28; SizeX_mm: 1.6; SizeY_mm: 0.8; EIA_Code: E96; U/M: EA; AEC Category: Q200
signal-integrity model Resistor
simulation model Resistor
footprint 0603
footprint 0603M
footprint 0603L
footprint 0603_HV
footprint 0603S
pins: 1, 2

## CRCW060329K4FKEA
designator R?  ValueDisplayed: 29.4k  (hidden comment: CRCW060329K4FKEA)
RES, 29.4 k, 1%, 0.1 W, 0603; Manufacturer: Vishay-Dale; CompType: Resistor; Value: 29.4k; Res_ohm: 29400; Value_Code: 29k4; Tolerance_%: 1; Power_W: 0.1; Value2: 0.1W; VDC_V: 75; TempCo: 100 ppm/C; SizeArea_mm2: 1.28; SizeX_mm: 1.6; SizeY_mm: 0.8; EIA_Code: E96; U/M: EA; AEC Category: Q200; Green_Lifecycle: Active; Green_REACh: Passed
signal-integrity model Resistor
simulation model Resistor
footprint 0603
footprint 0603M
footprint 0603L
footprint 0603_HV
footprint 0603S
pins: 1, 2

## CRCW060333K2FKEA
designator R?  ValueDisplayed: 33.2k  (hidden comment: CRCW060333K2FKEA)
RES, 33.2 k, 1%, 0.1 W, 0603; Manufacturer: Vishay-Dale; CompType: Resistor; Value: 33.2k; Res_ohm: 33200; Value_Code: 33k2; Tolerance_%: 1; Power_W: 0.1; Value2: 0.1W; VDC_V: 75; TempCo: 100 ppm/C; EIA_Code: E96; U/M: EA; AEC Category: Q200; SizeArea_mm2: 1.28; SizeX_mm: 1.6; SizeY_mm: 0.8; Green_Lifecycle: Active; Green_REACh: Passed
signal-integrity model Resistor
simulation model Resistor
footprint 0603
footprint 0603M
footprint 0603L
footprint 0603_HV
footprint 0603S
pins: 1, 2

## CRCW060334K0FKEA
designator R?  ValueDisplayed: 34.0k  (hidden comment: CRCW060334K0FKEA)
RES, 34.0 k, 1%, 0.1 W, 0603; Manufacturer: Vishay-Dale; CompType: Resistor; Value: 34.0k; Res_ohm: 34000; Value_Code: 34k0; Tolerance_%: 1; Power_W: 0.1; Value2: 0.1W; VDC_V: 75; TempCo: 100 ppm/C; EIA_Code: E96; U/M: EA; SizeArea_mm2: 1.28; SizeX_mm: 1.6; SizeY_mm: 0.8; AEC Category: Q200
signal-integrity model Resistor
simulation model Resistor
footprint 0603
footprint 0603M
footprint 0603L
footprint 0603_HV
footprint 0603S
pins: 1, 2

## CRCW060344K2FKEA
designator R?  ValueDisplayed: 44.2k  (hidden comment: CRCW060344K2FKEA)
RES, 44.2 k, 1%, 0.1 W, 0603; Manufacturer: Vishay-Dale; CompType: Resistor; Value: 44.2k; Res_ohm: 44200; Value_Code: 44k2; Tolerance_%: 1; Power_W: 0.1; Value2: 0.1W; VDC_V: 75; TempCo: 100 ppm/C; SizeArea_mm2: 1.28; SizeX_mm: 1.6; SizeY_mm: 0.8; EIA_Code: E96; U/M: EA; AEC Category: Q200
signal-integrity model Resistor
simulation model Resistor
footprint 0603
footprint 0603M
footprint 0603L
footprint 0603_HV
footprint 0603S
pins: 1, 2

## CRCW060349K9FKEA
designator R?  ValueDisplayed: 49.9k  (hidden comment: CRCW060349K9FKEA)
RES, 49.9 k, 1%, 0.1 W, 0603; Manufacturer: Vishay-Dale; CompType: Resistor; Value: 49.9k; Res_ohm: 49900; Value_Code: 49k9; Tolerance_%: 1; Power_W: 0.1; Value2: 0.1W; VDC_V: 75; TempCo: 100 ppm/C; EIA_Code: E96; U/M: EA; SizeArea_mm2: 1.28; SizeX_mm: 1.6; SizeY_mm: 0.8; AEC Category: Q200; Green_Lifecycle: Active; Green_REACh: Passed
signal-integrity model Resistor
simulation model Resistor
footprint 0603
footprint 0603M
footprint 0603L
footprint 0603_HV
footprint 0603S
pins: 1, 2

## CRCW060349R9FKEA
designator R?  ValueDisplayed: 49.9  (hidden comment: CRCW060349R9FKEA)
RES, 49.9, 1%, 0.1 W, 0603; Manufacturer: Vishay-Dale; CompType: Resistor; Value: 49.9; Value_Code: 49R9; Tolerance_%: 1; Power_W: 0.1; Value2: 0.1W; VDC_V: 75; TempCo: 100 ppm/C; SizeArea_mm2: 1.28; SizeX_mm: 1.6; SizeY_mm: 0.8; EIA_Code: E96; U/M: EA; AEC Category: Q200; Green_Lifecycle: Active; Green_REACh: Passed
signal-integrity model Resistor
simulation model Resistor
footprint 0603
footprint 0603M
footprint 0603L
footprint 0603_HV
footprint 0603S
pins: 1, 2

## CRCW060351R0JNEA
designator R?  ValueDisplayed: 51  (hidden comment: CRCW060351R0JNEA)
RES, 51, 5%, 0.1 W, 0603; Manufacturer: Vishay-Dale; CompType: Resistor; Value: 51; Value_Code: 51R0; Tolerance_%: 5; Power_W: 0.1; Value2: 0.1W; VDC_V: 75; TempCo: 200 ppm/C; EIA_Code: E24; U/M: EA; AEC Category: Q200
signal-integrity model Resistor
simulation model Resistor
footprint 0603
footprint 0603M
footprint 0603L
footprint 0603_HV
footprint 0603S
pins: 1, 2

## CRCW060361K9FKEA
designator R?  ValueDisplayed: 61.9k  (hidden comment: CRCW060361K9FKEA)
RES, 61.9 k, 1%, 0.1 W, 0603; Manufacturer: Vishay-Dale; CompType: Resistor; Value: 61.9k; Res_ohm: 61900; Value_Code: 61k9; Tolerance_%: 1; Power_W: 0.1; Value2: 0.1W; VDC_V: 75; TempCo: 100 ppm/C; EIA_Code: E96; U/M: EA
signal-integrity model Resistor
simulation model Resistor
footprint 0603
footprint 0603M
footprint 0603L
footprint 0603_HV
footprint 0603S
pins: 1, 2

## CRCW060380K6FKEA
designator R?  ValueDisplayed: 80.6k  (hidden comment: CRCW060380K6FKEA)
RES, 80.6 k, 1%, 0.1 W, 0603; Manufacturer: Vishay-Dale; CompType: Resistor; Value: 80.6k; Res_ohm: 80600; Value_Code: 80k6; Tolerance_%: 1; Power_W: 0.1; Value2: 0.1W; VDC_V: 75; TempCo: 100 ppm/C; EIA_Code: E96; U/M: EA; AEC Category: Q200; SizeArea_mm2: 1.28; SizeX_mm: 1.6; SizeY_mm: 0.8; Green_Lifecycle: Active; Green_REACh: Passed
signal-integrity model Resistor
simulation model Resistor
footprint 0603
footprint 0603M
footprint 0603L
footprint 0603_HV
footprint 0603S
pins: 1, 2

## CRCW0402100KFKED
designator R?  ValueDisplayed: 100k  (hidden comment: CRCW0402100KFKED)
RES, 100 k, 1%, 0.063 W, 0402; Manufacturer: Vishay-Dale; CompType: Resistor; Value: 100k; Res_ohm: 100000; Tolerance_%: 1; Power_W: 0.063; Value2: 0.063W; VDC_V: 50; TempCo: 100 ppm/C; EIA_Code: E96; U/M: EA; AEC Category: Q200
signal-integrity model Resistor
simulation model Resistor
footprint 0402
footprint 0402M
footprint 0402L
footprint 0402S
pins: 1, 2

## CRCW0402294KFKED
designator R?  ValueDisplayed: 294k  (hidden comment: CRCW0402294KFKED)
RES, 294 k, 1%, 0.063 W, 0402; Manufacturer: Vishay-Dale; CompType: Resistor; Value: 294k; Res_ohm: 294000; Tolerance_%: 1; Power_W: 0.063; Value2: 0.063W; VDC_V: 50; TempCo: 100 ppm/C; EIA_Code: E96; U/M: EA; AEC Category: Q200
signal-integrity model Resistor
simulation model Resistor
footprint 0402
footprint 0402M
footprint 0402L
footprint 0402S
pins: 1, 2

## CRCW0402357KFKED
designator R?  ValueDisplayed: 357k  (hidden comment: CRCW0402357KFKED)
RES, 357 k, 1%, 0.063 W, 0402; Manufacturer: Vishay-Dale; CompType: Resistor; Value: 357k; Res_ohm: 357000; Tolerance_%: 1; Power_W: 0.063; Value2: 0.063W; VDC_V: 50; TempCo: 100 ppm/C; EIA_Code: E96; U/M: EA; AEC Category: Q200
signal-integrity model Resistor
simulation model Resistor
footprint 0402
footprint 0402M
footprint 0402L
footprint 0402S
pins: 1, 2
